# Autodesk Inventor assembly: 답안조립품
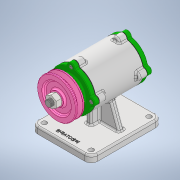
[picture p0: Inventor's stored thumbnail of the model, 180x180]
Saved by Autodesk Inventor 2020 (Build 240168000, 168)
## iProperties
Created: 2022-11
Part Number: 답안조립품
Document SubType Name: Assembly
Designer: owner
Author: owner
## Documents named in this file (12)
- C:\Users\owner\Desktop\721108V1018\답안조립품.iam
- C:\Users\owner\Desktop\721108V1018\본체.ipt
- C:\Users\owner\Desktop\721108V1018\V-벨트풀리.ipt
- C:\Users\owner\Desktop\721108V1018\개스킷.ipt
- C:\Users\owner\Desktop\721108V1018\너트 M12 x 1.25.ipt
- C:\Users\owner\Desktop\721108V1018\뒤커버.ipt
- C:\Users\owner\Desktop\721108V1018\베어링 6204.ipt
- C:\Users\owner\Desktop\721108V1018\볼트 M4 x 12.ipt
- C:\Users\owner\Desktop\721108V1018\앞커버.ipt
- C:\Users\owner\Desktop\721108V1018\오일 실.ipt
- C:\Users\owner\Desktop\721108V1018\축.ipt
- C:\Users\owner\Desktop\721108V1018\키 4 x 4.ipt
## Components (8 placed, 6 different names)
1. V-벨트풀리:1 — 각도:1
2. 개스킷:1
3. KS B 1012 클래스 1 일반 - 미터 M12x1.25:1 — 각도:1
4. KS B 2023 6204 - 20 x 47 x 14:1
5. KS B 2804 D D - 20 32 8:1 — 플러쉬:1
6. KS B 1311 (I) 4 x 4 x 12:1
7. 개스킷:2
8. KS B 2023 6204 - 20 x 47 x 14:2
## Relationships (2: Flush 1, Angle 1)
- 플러쉬:1 [Flush]: KS B 2804 D D - 20 32 8:1
- 각도:1 [Angle]: V-벨트풀리:1 ↔ KS B 1012 클래스 1 일반 - 미터 M12x1.25:1
